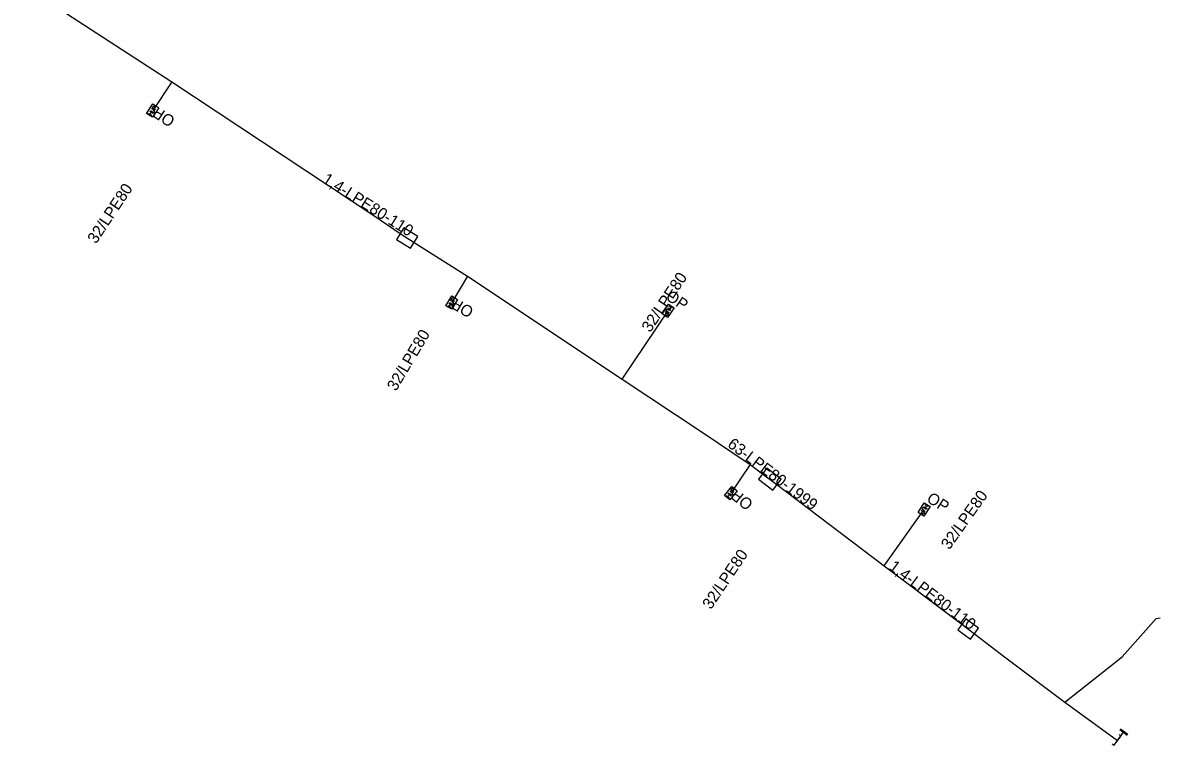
# Model space of a CAD drawing. Extents: x -762509 to -761250, y -1153000 to -1152256.
# Drawn here: x -761349.2 to -761250, y -1152621.7 to -1152558.6 of the extents above; entities that cross this region are included whole.
import ezdxf

# ---------------------------------------------------------------- set-up
doc = ezdxf.new("R2010")
doc.units = 0
for name, color, linetype in [('Vrstva 21', 7, 'Continuous'), ('Vrstva 23', 7, 'Continuous'), ('Vrstva 24', 7, 'Continuous'), ('Vrstva 29', 7, 'Continuous'), ('Vrstva 31', 7, 'Continuous'), ('Vrstva 32', 7, 'Continuous')]:
    doc.layers.add(name, color=color, linetype=linetype)

msp = doc.modelspace()

# ---------------------------------------------------------------- linework, layer by layer
at = {"layer": 'Vrstva 21'}
for points in [[(-761349.19, -1152555.34), (-761336.19, -1152563.79), (-761318.59, -1152575.45), (-761316.27, -1152577.04), (-761315.05, -1152577.81), (-761310.42, -1152580.76), (-761296.93, -1152589.74), (-761289.95, -1152594.37), (-761285.76, -1152597.17), (-761284.68, -1152597.98), (-761283.43, -1152598.93), (-761274.08, -1152606.02), (-761267.3, -1152611.11), (-761266.2, -1152611.94), (-761263.46, -1152614.04), (-761258.31, -1152617.9)], [(-761258.31, -1152617.9), (-761253.32, -1152613.95), (-761250.37, -1152610.62), (-761250, -1152610.55)], [(-761258.31, -1152617.9), (-761253.73, -1152621.26)]]:
    msp.add_lwpolyline(points, dxfattribs=at)
at = {"layer": 'Vrstva 23'}
msp.add_lwpolyline([(-761254.187, -1152621.544), (-761254.026, -1152621.663), (-761253.435, -1152620.856), (-761253.596, -1152620.738)], dxfattribs=at)
at = {"layer": 'Vrstva 24'}
for p, q in [((-761253.52, -1152620.298), (-761252.875, -1152620.771)), ((-761253.461, -1152620.218), (-761252.816, -1152620.691)), ((-761253.73, -1152621.26), (-761253.197, -1152620.535))]:
    msp.add_line(p, q, dxfattribs=at)
at = {"layer": 'Vrstva 29'}
for points in [[(-761316.59, -1152577.55), (-761315.37, -1152578.32), (-761314.73, -1152577.3), (-761315.95, -1152576.53)], [(-761285.04, -1152598.46), (-761283.79, -1152599.41), (-761283.07, -1152598.45), (-761284.32, -1152597.5)], [(-761267.66, -1152611.59), (-761266.56, -1152612.42), (-761265.84, -1152611.46), (-761266.94, -1152610.63)]]:
    msp.add_lwpolyline(points, close=True, dxfattribs=at)
at = {"layer": 'Vrstva 31'}
for points in [[(-761336.19, -1152563.79), (-761337.86, -1152566.31)], [(-761310.42, -1152580.76), (-761311.78, -1152583.05)], [(-761296.93, -1152589.74), (-761292.92, -1152583.77)], [(-761285.76, -1152597.17), (-761287.44, -1152599.67)], [(-761274.08, -1152606.02), (-761270.59, -1152601.09)]]:
    msp.add_lwpolyline(points, dxfattribs=at)
at = {"layer": 'Vrstva 32'}
for p, q in [((-761338.227, -1152566.547), (-761337.935, -1152566.74)), ((-761337.824, -1152566.573), (-761338.116, -1152566.379)), ((-761338.089, -1152566.638), (-761337.978, -1152566.47)), ((-761337.604, -1152566.24), (-761337.895, -1152566.047)), ((-761311.527, -1152582.968), (-761311.828, -1152582.789)), ((-761312.135, -1152583.305), (-761311.834, -1152583.484)), ((-761311.731, -1152583.311), (-761312.032, -1152583.132)), ((-761311.993, -1152583.389), (-761311.89, -1152583.216)), ((-761292.952, -1152583.507), (-761292.663, -1152583.704)), ((-761292.549, -1152583.538), (-761292.839, -1152583.341)), ((-761292.686, -1152583.445), (-761292.799, -1152583.611)), ((-761293.177, -1152583.837), (-761292.888, -1152584.034)), ((-761287.178, -1152599.625), (-761287.45, -1152599.405)), ((-761287.827, -1152599.871), (-761287.555, -1152600.091)), ((-761287.429, -1152599.935), (-761287.701, -1152599.715)), ((-761287.699, -1152599.975), (-761287.573, -1152599.819)), ((-761270.229, -1152600.845), (-761270.525, -1152600.659)), ((-761270.845, -1152601.166), (-761270.549, -1152601.353)), ((-761270.632, -1152600.829), (-761270.336, -1152601.015)), ((-761270.369, -1152600.757), (-761270.476, -1152600.927))]:
    msp.add_line(p, q, dxfattribs=at)
for points in [[(-761338.386, -1152566.561), (-761337.834, -1152565.728), (-761337.334, -1152566.059), (-761337.886, -1152566.893), (-761338.386, -1152566.561)], [(-761337.895, -1152566.047), (-761337.824, -1152565.938), (-761337.786, -1152565.913), (-761337.765, -1152565.909), (-761337.729, -1152565.916), (-761337.688, -1152565.943), (-761337.668, -1152565.973), (-761337.663, -1152565.995), (-761337.672, -1152566.039), (-761337.744, -1152566.147)], [(-761338.061, -1152566.297), (-761337.852, -1152566.435), (-761337.803, -1152566.451), (-761337.759, -1152566.443), (-761337.721, -1152566.418), (-761337.705, -1152566.393), (-761337.696, -1152566.349), (-761337.708, -1152566.307), (-761337.741, -1152566.268), (-761337.95, -1152566.129)], [(-761312.293, -1152583.327), (-761311.783, -1152582.467), (-761311.267, -1152582.774), (-761311.777, -1152583.633), (-761312.293, -1152583.327)], [(-761311.828, -1152582.789), (-761311.762, -1152582.677), (-761311.726, -1152582.65), (-761311.705, -1152582.645), (-761311.669, -1152582.65), (-761311.626, -1152582.675), (-761311.605, -1152582.704), (-761311.599, -1152582.725), (-761311.606, -1152582.77), (-761311.672, -1152582.882)], [(-761311.982, -1152583.047), (-761311.766, -1152583.175), (-761311.716, -1152583.188), (-761311.672, -1152583.178), (-761311.636, -1152583.151), (-761311.621, -1152583.126), (-761311.615, -1152583.081), (-761311.628, -1152583.039), (-761311.663, -1152583.002), (-761311.879, -1152582.874)], [(-761292.39, -1152583.526), (-761292.954, -1152584.352), (-761293.449, -1152584.014), (-761292.885, -1152583.188), (-761292.39, -1152583.526)], [(-761292.719, -1152583.786), (-761292.926, -1152583.645), (-761292.974, -1152583.629), (-761293.019, -1152583.636), (-761293.057, -1152583.661), (-761293.073, -1152583.685), (-761293.083, -1152583.729), (-761293.072, -1152583.771), (-761293.039, -1152583.811), (-761292.832, -1152583.952)], [(-761292.888, -1152584.034), (-761292.961, -1152584.141), (-761292.999, -1152584.166), (-761293.021, -1152584.17), (-761293.056, -1152584.163), (-761293.097, -1152584.134), (-761293.116, -1152584.104), (-761293.121, -1152584.083), (-761293.111, -1152584.039), (-761293.038, -1152583.931)], [(-761287.987, -1152599.87), (-761287.358, -1152599.093), (-761286.892, -1152599.47), (-761287.521, -1152600.248), (-761287.987, -1152599.87)], [(-761287.639, -1152599.638), (-761287.444, -1152599.796), (-761287.397, -1152599.816), (-761287.351, -1152599.813), (-761287.312, -1152599.791), (-761287.294, -1152599.768), (-761287.28, -1152599.725), (-761287.288, -1152599.681), (-761287.317, -1152599.64), (-761287.512, -1152599.482)], [(-761287.45, -1152599.405), (-761287.368, -1152599.304), (-761287.329, -1152599.282), (-761287.307, -1152599.28), (-761287.272, -1152599.29), (-761287.233, -1152599.322), (-761287.217, -1152599.353), (-761287.214, -1152599.375), (-761287.227, -1152599.418), (-761287.308, -1152599.519)], [(-761270.07, -1152600.827), (-761270.603, -1152601.673), (-761271.111, -1152601.353), (-761270.578, -1152600.507), (-761270.07, -1152600.827)], [(-761270.549, -1152601.353), (-761270.618, -1152601.463), (-761270.655, -1152601.489), (-761270.677, -1152601.494), (-761270.712, -1152601.488), (-761270.754, -1152601.461), (-761270.775, -1152601.432), (-761270.78, -1152601.41), (-761270.772, -1152601.366), (-761270.703, -1152601.256)], [(-761270.389, -1152601.099), (-761270.601, -1152600.965), (-761270.65, -1152600.951), (-761270.695, -1152600.96), (-761270.731, -1152600.986), (-761270.747, -1152601.011), (-761270.755, -1152601.055), (-761270.743, -1152601.097), (-761270.709, -1152601.135), (-761270.496, -1152601.269)]]:
    msp.add_lwpolyline(points, dxfattribs=at)

# ---------------------------------------------------------------- texts
at = {"layer": 'Vrstva 21'}
msp.add_text('63-LPE80-1999', height=1, rotation=322.82737, dxfattribs=at).set_placement((-761287.81, -1152595.57))
at = {"layer": 'Vrstva 29'}
for rotation, p in [(327.74203, (-761323.14, -1152572.53)), (322.96379, (-761273.73, -1152606.25))]:
    msp.add_text('1,4-LPE80-110', height=1, rotation=rotation, dxfattribs=at).set_placement(p)
at = {"layer": 'Vrstva 31'}
for rotation, p in [(56.46763, (-761342.8, -1152577.99)), (56.46763, (-761342.8, -1152577.99)), (56.11107, (-761294.48, -1152585.72)), (56.11107, (-761294.48, -1152585.72)), (59.2945, (-761316.64, -1152590.84)), (59.2945, (-761316.64, -1152590.84)), (54.70491, (-761268.39, -1152604.67)), (54.70491, (-761268.39, -1152604.67)), (56.0989, (-761289.18, -1152609.88)), (56.0989, (-761289.18, -1152609.88))]:
    msp.add_text('32/LPE80', height=1, rotation=rotation, dxfattribs=at).set_placement(p)
at = {"layer": 'Vrstva 32'}
for rotation, p in [(146.46763, (-761335.82, -1152566.98)), (146.46763, (-761335.82, -1152566.98)), (325.6737, (-761293.2, -1152582.72)), (325.6737, (-761293.2, -1152582.72)), (149.2945, (-761309.78, -1152583.59)), (149.2945, (-761309.78, -1152583.59)), (141.02574, (-761285.42, -1152600.48)), (141.02574, (-761285.42, -1152600.48)), (327.77373, (-761270.45, -1152600.37)), (327.77373, (-761270.45, -1152600.37))]:
    msp.add_text('OP', height=1, rotation=rotation, dxfattribs=at).set_placement(p)

doc.saveas('drawing.dxf')
